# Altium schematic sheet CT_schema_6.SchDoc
size 278 x 170 mm
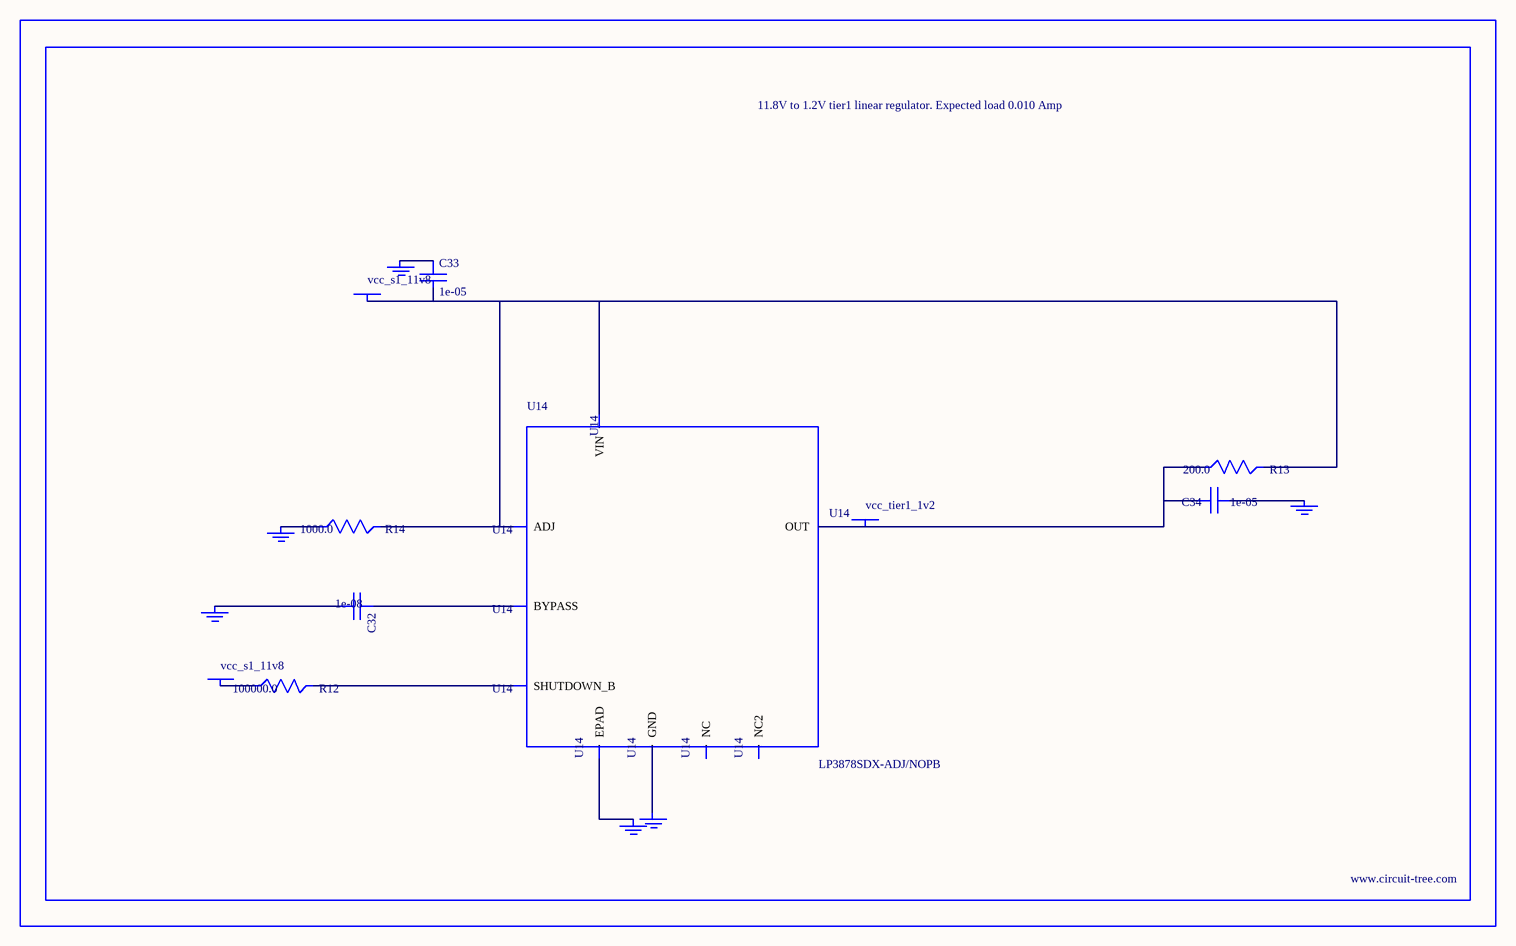
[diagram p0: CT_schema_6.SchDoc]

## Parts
BORDER5  (no value)
C32  1e-08  [C0402]
C33  1e-05  [C1210]
C34  1e-05  [C0805]
GND_INSTANCE_5_0  (no value)
GND_INSTANCE_5_1  (no value)
GND_INSTANCE_5_2  (no value)
GND_INSTANCE_5_3  (no value)
GND_INSTANCE_5_4  (no value)
GND_INSTANCE_5_5  (no value)
POWER_INSTANCE_5_0  vcc_s1_11v8
POWER_INSTANCE_5_1  vcc_s1_11v8
POWER_INSTANCE_5_2  vcc_tier1_1v2
R12  100000.0  [R0603]
R13  200.0  [R0603]
R14  1000.0  [R0603]
U14  LP3878SDX-ADJ/NOPB  [WSON-8]

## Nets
NetC32_1: C32.1 U14.1(BYPASS)
NetC32_2: C32.2 GND_INSTANCE_5_0.0(GND)
NetC33_1: C33.1 GND_INSTANCE_5_1.0(GND)
NetC33_2: C33.2 POWER_INSTANCE_5_0.0(PWR) R13.2 R14.2 U14.4(VIN) U14.6(ADJ)
NetC34_1: C34.1 GND_INSTANCE_5_2.0(GND)
NetC34_2: C34.2 POWER_INSTANCE_5_2.0(PWR) R13.1 U14.5(OUT)
NetGND_INSTANCE_5_3_0: GND_INSTANCE_5_3.0(GND) R14.1
NetGND_INSTANCE_5_4_0: GND_INSTANCE_5_4.0(GND) U14.PAD(EPAD)
NetGND_INSTANCE_5_5_0: GND_INSTANCE_5_5.0(GND) U14.3(GND)
NetPOWER_INSTANCE_5_1_0: POWER_INSTANCE_5_1.0(PWR) R12.1
NetR12_2: R12.2 U14.8(SHUTDOWN_B)

Not connected (* = marked no-connect by the designer): U14 2(NC) 7(NC2)

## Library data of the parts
BORDER5 = BORDER_PAGE5
C32 = C0402C103K3RAC
C33 = C1210C106K5PACTU
C34 = GRM219R60J106ME19D
GND_INSTANCE_5_0-GND_INSTANCE_5_5 = GND
POWER_INSTANCE_5_0-POWER_INSTANCE_5_2 = PWR
R12 = RC0603JR-07100KL
R13 = RC0603JR-07200RL
R14 = RC0603JR-071KL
